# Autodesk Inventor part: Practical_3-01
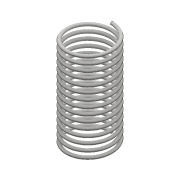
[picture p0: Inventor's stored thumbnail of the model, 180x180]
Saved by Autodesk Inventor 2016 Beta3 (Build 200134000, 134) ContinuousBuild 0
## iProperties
Created: 2016-02
Part Number: Practical_3-01
Material: Generic
Document SubType Name: Modeling
Designer: Gaurav
Density: 1 g/cm^3
Appearance: Default
Author: Gaurav
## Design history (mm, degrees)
sketch "Sketch1"
  geometry: L1 (0, 0)-(0, -150); C1 r 2.5 at (35, 0)
  constraints: 2 end point, 1 centre point, 1 vertical
  dimensions: "d0" = 150 distance of L1.start L1.end; "d1" = 5 diameter of C1; "d2" = 35 distance of C1.centre L1.start
coil "Coil3" sketch "Sketch1" pitch "d19" = 10; turns "d21" = 10; dims "d20" = 150, "d22" = 0, angle "d23" = 90 deg, angle "d24" = 90 deg, "d25" = 0, "d26" = 0
body "Solid3"
